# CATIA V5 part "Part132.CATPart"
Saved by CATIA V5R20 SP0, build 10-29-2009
Part number: 9FA 084712
Revision: ANY
Definition: UNKNOWN
Nomenclature: 9FA 084712
Source: Unknown
Bounding box of the stored display mesh (mm): x -4 to 3.804, y -10 to 10, z -4 to 4
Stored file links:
  C:\Users\Utente\Desktop\IO LAVORO\3D X SITO CF\CUMSA\3D files FA\FA 084712-20\Part132.CATPart

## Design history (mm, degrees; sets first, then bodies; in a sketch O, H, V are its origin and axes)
Body1 "Cortar-Extruir5" (main body)
  Solid1: solid without history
